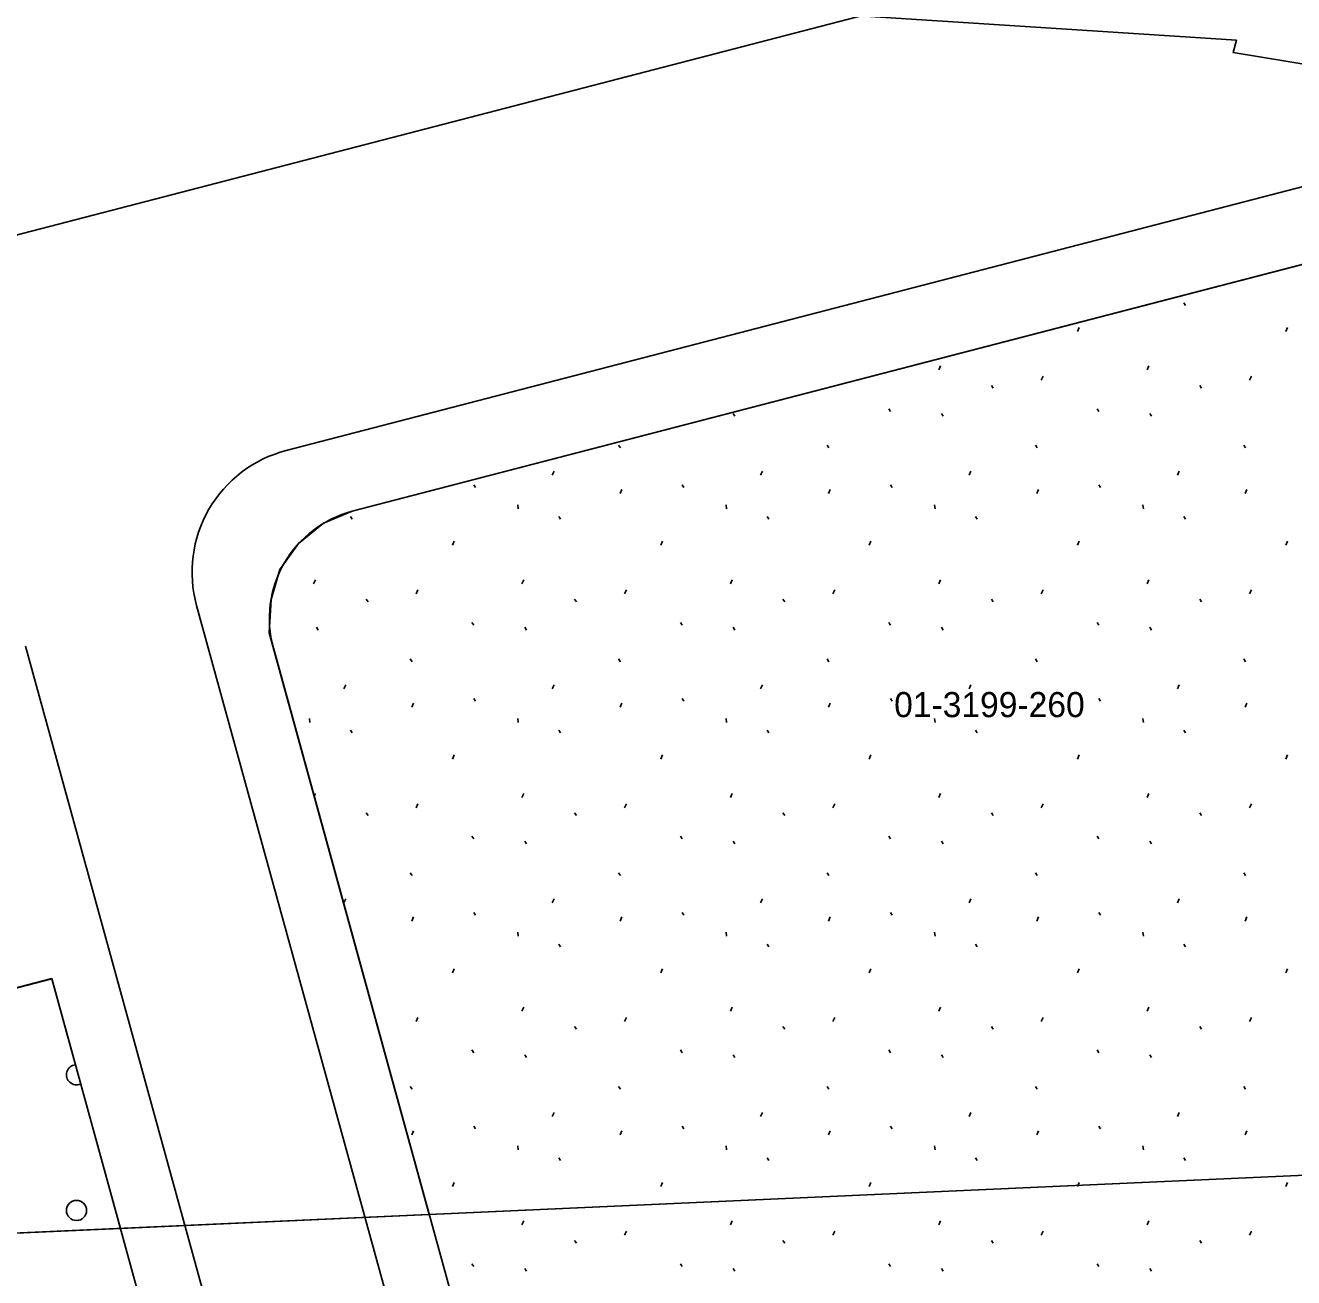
# Model space of a CAD drawing. Extents: x 419396 to 421519, y 4453567 to 4456767.
# Drawn here: x 421061.6 to 421112.1, y 4454776.6 to 4454826.5 of the extents above; entities that cross this region are included whole.
import ezdxf

# ---------------------------------------------------------------- set-up
doc = ezdxf.new("R2010")
doc.units = 0
for name, color, linetype in [('0_KADASTRO', 7, 'Continuous'), ('Level 28', 7, 'Continuous'), ('Level 41', 7, 'Continuous'), ('Level 43', 7, 'Continuous'), ('Level 62', 7, 'Continuous')]:
    doc.layers.add(name, color=color, linetype=linetype)

msp = doc.modelspace()

# ---------------------------------------------------------------- linework, layer by layer
at = {"layer": '0_KADASTRO'}
for points in [[(421028.757, 4454779.729), (421031.18, 4454814.37), (421031.268, 4454815.21), (421037.79, 4454815.4), (421037.91, 4454827.443), (421072.693, 4454827.787), (421077.33, 4454827.7), (421089.42, 4454827.23), (421092.96, 4454826.99), (421103.25, 4454826.33), (421109.8, 4454825.9), (421109.67, 4454825.41), (421112.98, 4454824.87), (421121.89, 4454821.45), (421122.04, 4454819.47), (421074.61, 4454807.15), (421073.47, 4454806.68), (421072.47, 4454805.87), (421071.73, 4454804.83), (421071.38, 4454803.63), (421071.31, 4454802.31), (421077.68, 4454779.15), (421065.39, 4454778.6), (421062.65, 4454788.54)], [(421071.31, 4454802.31), (421071.38, 4454803.63), (421071.73, 4454804.83), (421072.47, 4454805.87), (421073.47, 4454806.68), (421074.61, 4454807.15), (421122.04, 4454819.47), (421122.53, 4454812.93), (421122.63, 4454800.46), (421122.46, 4454786.27), (421122.61, 4454779.98), (421116.99, 4454780.91), (421077.68, 4454779.15)], [(421028.563, 4454776.952), (421028.757, 4454779.729), (421062.65, 4454788.54), (421065.39, 4454778.6)]]:
    msp.add_lwpolyline(points, close=True, dxfattribs=at)
msp.add_lwpolyline([(420970.25, 4454598.21), (420978.09, 4454629.67), (420985.81, 4454647.83), (420992.78, 4454658.3), (420990.74, 4454672.41), (420973.683, 4454711.074), (420973.63, 4454711.21), (420957.38, 4454751.82), (420949.17, 4454769.71), (421010.39, 4454774.36), (421028.563, 4454776.952), (421116.99, 4454780.91)], dxfattribs=at)
at = {"layer": 'Level 28'}
for p, q in [((421074.613, 4454807.147), (421123.795, 4454819.928)), ((421092.049, 4454726.945), (421071.472, 4454801.712)), ((420975.535, 4454765.902), (421062.651, 4454788.541)), ((421062.651, 4454788.541), (421085.345, 4454706.078))]:
    msp.add_line(p, q, dxfattribs=at)
msp.add_arc((421075.722, 4454802.881), 4.408, 104.5669, 195.3875, dxfattribs=at)
at = {"layer": 'Level 41'}
for p, q in [((421110.152, 4454816.366), (421110.161, 4454816.386)), ((421107.712, 4454815.45), (421107.782, 4454815.343)), ((421103.475, 4454814.306), (421103.547, 4454814.466)), ((421111.768, 4454814.306), (421111.84, 4454814.466)), ((421097.954, 4454812.776), (421098.024, 4454812.936)), ((421106.247, 4454812.776), (421106.317, 4454812.936)), ((421102.037, 4454812.368), (421102.108, 4454812.528)), ((421110.33, 4454812.368), (421110.401, 4454812.528)), ((421100.049, 4454812.16), (421100.12, 4454812.054)), ((421108.342, 4454812.16), (421108.413, 4454812.054)), ((421089.77, 4454811.039), (421089.841, 4454810.932)), ((421095.964, 4454811.231), (421096.035, 4454811.124)), ((421098.063, 4454811.039), (421098.134, 4454810.932)), ((421104.257, 4454811.231), (421104.328, 4454811.124)), ((421106.356, 4454811.039), (421106.427, 4454810.932)), ((421085.215, 4454809.778), (421085.286, 4454809.671)), ((421093.508, 4454809.778), (421093.579, 4454809.671)), ((421101.801, 4454809.778), (421101.872, 4454809.671)), ((421110.094, 4454809.778), (421110.165, 4454809.671)), ((421082.574, 4454808.585), (421082.645, 4454808.744)), ((421090.867, 4454808.585), (421090.938, 4454808.744)), ((421099.16, 4454808.585), (421099.231, 4454808.744)), ((421107.453, 4454808.585), (421107.524, 4454808.744)), ((421079.445, 4454808.201), (421079.516, 4454808.094)), ((421085.273, 4454807.856), (421085.345, 4454808.016)), ((421087.738, 4454808.201), (421087.809, 4454808.094)), ((421093.566, 4454807.856), (421093.638, 4454808.016)), ((421096.031, 4454808.201), (421096.102, 4454808.094)), ((421101.859, 4454807.856), (421101.931, 4454808.016)), ((421104.324, 4454808.201), (421104.395, 4454808.094)), ((421110.152, 4454807.856), (421110.224, 4454808.016)), ((421081.203, 4454807.41), (421081.221, 4454807.25)), ((421089.496, 4454807.41), (421089.514, 4454807.25)), ((421097.789, 4454807.41), (421097.807, 4454807.25)), ((421106.082, 4454807.41), (421106.1, 4454807.25)), ((421074.54, 4454806.94), (421074.61, 4454806.833)), ((421082.833, 4454806.94), (421082.903, 4454806.833)), ((421091.126, 4454806.94), (421091.196, 4454806.833)), ((421099.419, 4454806.94), (421099.489, 4454806.833)), ((421107.712, 4454806.94), (421107.782, 4454806.833)), ((421078.596, 4454805.796), (421078.668, 4454805.956)), ((421086.889, 4454805.796), (421086.961, 4454805.956)), ((421095.182, 4454805.796), (421095.254, 4454805.956)), ((421103.475, 4454805.796), (421103.547, 4454805.956)), ((421111.768, 4454805.796), (421111.84, 4454805.956)), ((421073.075, 4454804.266), (421073.145, 4454804.426)), ((421081.368, 4454804.266), (421081.438, 4454804.426)), ((421089.661, 4454804.266), (421089.731, 4454804.426)), ((421097.954, 4454804.266), (421098.024, 4454804.426)), ((421106.247, 4454804.266), (421106.317, 4454804.426)), ((421077.158, 4454803.858), (421077.229, 4454804.018)), ((421085.451, 4454803.858), (421085.522, 4454804.018)), ((421093.744, 4454803.858), (421093.815, 4454804.018)), ((421102.037, 4454803.858), (421102.108, 4454804.018)), ((421110.33, 4454803.858), (421110.401, 4454804.018)), ((421075.17, 4454803.65), (421075.241, 4454803.544)), ((421083.463, 4454803.65), (421083.534, 4454803.544)), ((421091.756, 4454803.65), (421091.827, 4454803.544)), ((421100.049, 4454803.65), (421100.12, 4454803.544)), ((421108.342, 4454803.65), (421108.413, 4454803.544)), ((421073.184, 4454802.529), (421073.255, 4454802.422)), ((421079.378, 4454802.721), (421079.449, 4454802.614)), ((421081.477, 4454802.529), (421081.548, 4454802.422)), ((421087.671, 4454802.721), (421087.742, 4454802.614)), ((421089.77, 4454802.529), (421089.841, 4454802.422)), ((421095.964, 4454802.721), (421096.035, 4454802.614)), ((421098.063, 4454802.529), (421098.134, 4454802.422)), ((421104.257, 4454802.721), (421104.328, 4454802.614)), ((421106.356, 4454802.529), (421106.427, 4454802.422)), ((421076.922, 4454801.268), (421076.993, 4454801.161)), ((421085.215, 4454801.268), (421085.286, 4454801.161)), ((421093.508, 4454801.268), (421093.579, 4454801.161)), ((421101.801, 4454801.268), (421101.872, 4454801.161)), ((421110.094, 4454801.268), (421110.165, 4454801.161)), ((421074.281, 4454800.075), (421074.352, 4454800.234)), ((421082.574, 4454800.075), (421082.645, 4454800.234)), ((421090.867, 4454800.075), (421090.938, 4454800.234)), ((421099.16, 4454800.075), (421099.231, 4454800.234)), ((421107.453, 4454800.075), (421107.524, 4454800.234)), ((421076.98, 4454799.346), (421077.052, 4454799.506)), ((421079.445, 4454799.691), (421079.516, 4454799.584)), ((421085.273, 4454799.346), (421085.345, 4454799.506)), ((421087.738, 4454799.691), (421087.809, 4454799.584)), ((421093.566, 4454799.346), (421093.638, 4454799.506)), ((421096.031, 4454799.691), (421096.102, 4454799.584)), ((421101.859, 4454799.346), (421101.931, 4454799.506)), ((421104.324, 4454799.691), (421104.395, 4454799.584)), ((421110.152, 4454799.346), (421110.224, 4454799.506)), ((421072.91, 4454798.9), (421072.928, 4454798.74)), ((421081.203, 4454798.9), (421081.221, 4454798.74)), ((421089.496, 4454798.9), (421089.514, 4454798.74)), ((421097.789, 4454798.9), (421097.807, 4454798.74)), ((421106.082, 4454798.9), (421106.1, 4454798.74)), ((421074.54, 4454798.43), (421074.61, 4454798.323)), ((421082.833, 4454798.43), (421082.903, 4454798.323)), ((421091.126, 4454798.43), (421091.196, 4454798.323)), ((421099.419, 4454798.43), (421099.489, 4454798.323)), ((421107.712, 4454798.43), (421107.782, 4454798.323)), ((421078.596, 4454797.286), (421078.668, 4454797.446)), ((421086.889, 4454797.286), (421086.961, 4454797.446)), ((421095.182, 4454797.286), (421095.254, 4454797.446)), ((421103.475, 4454797.286), (421103.547, 4454797.446)), ((421111.768, 4454797.286), (421111.84, 4454797.446)), ((421073.098, 4454795.808), (421073.145, 4454795.916)), ((421081.368, 4454795.756), (421081.438, 4454795.916)), ((421089.661, 4454795.756), (421089.731, 4454795.916)), ((421097.954, 4454795.756), (421098.024, 4454795.916)), ((421106.247, 4454795.756), (421106.317, 4454795.916)), ((421077.158, 4454795.348), (421077.229, 4454795.508)), ((421085.451, 4454795.348), (421085.522, 4454795.508)), ((421093.744, 4454795.348), (421093.815, 4454795.508)), ((421102.037, 4454795.348), (421102.108, 4454795.508)), ((421110.33, 4454795.348), (421110.401, 4454795.508)), ((421075.17, 4454795.14), (421075.241, 4454795.034)), ((421083.463, 4454795.14), (421083.534, 4454795.034)), ((421091.756, 4454795.14), (421091.827, 4454795.034)), ((421100.049, 4454795.14), (421100.12, 4454795.034)), ((421108.342, 4454795.14), (421108.413, 4454795.034)), ((421079.378, 4454794.211), (421079.449, 4454794.104)), ((421087.671, 4454794.211), (421087.742, 4454794.104)), ((421095.964, 4454794.211), (421096.035, 4454794.104)), ((421104.257, 4454794.211), (421104.328, 4454794.104)), ((421081.477, 4454794.019), (421081.548, 4454793.912)), ((421089.77, 4454794.019), (421089.841, 4454793.912)), ((421098.063, 4454794.019), (421098.134, 4454793.912)), ((421106.356, 4454794.019), (421106.427, 4454793.912)), ((421076.922, 4454792.758), (421076.993, 4454792.651)), ((421085.215, 4454792.758), (421085.286, 4454792.651)), ((421093.508, 4454792.758), (421093.579, 4454792.651)), ((421101.801, 4454792.758), (421101.872, 4454792.651)), ((421110.094, 4454792.758), (421110.165, 4454792.651)), ((421074.281, 4454791.565), (421074.352, 4454791.724)), ((421082.574, 4454791.565), (421082.645, 4454791.724)), ((421090.867, 4454791.565), (421090.938, 4454791.724)), ((421099.16, 4454791.565), (421099.231, 4454791.724)), ((421107.453, 4454791.565), (421107.524, 4454791.724)), ((421079.445, 4454791.181), (421079.516, 4454791.074)), ((421087.738, 4454791.181), (421087.809, 4454791.074)), ((421096.031, 4454791.181), (421096.102, 4454791.074)), ((421104.324, 4454791.181), (421104.395, 4454791.074)), ((421076.98, 4454790.836), (421077.052, 4454790.996)), ((421085.273, 4454790.836), (421085.345, 4454790.996)), ((421093.566, 4454790.836), (421093.638, 4454790.996)), ((421101.859, 4454790.836), (421101.931, 4454790.996)), ((421110.152, 4454790.836), (421110.224, 4454790.996)), ((421081.203, 4454790.39), (421081.221, 4454790.23)), ((421089.496, 4454790.39), (421089.514, 4454790.23)), ((421097.789, 4454790.39), (421097.807, 4454790.23)), ((421106.082, 4454790.39), (421106.1, 4454790.23)), ((421082.833, 4454789.92), (421082.903, 4454789.813)), ((421091.126, 4454789.92), (421091.196, 4454789.813)), ((421099.419, 4454789.92), (421099.489, 4454789.813)), ((421107.712, 4454789.92), (421107.782, 4454789.813)), ((421078.596, 4454788.776), (421078.668, 4454788.936)), ((421086.889, 4454788.776), (421086.961, 4454788.936)), ((421095.182, 4454788.776), (421095.254, 4454788.936)), ((421103.475, 4454788.776), (421103.547, 4454788.936)), ((421111.768, 4454788.776), (421111.84, 4454788.936)), ((421081.368, 4454787.246), (421081.438, 4454787.406)), ((421089.661, 4454787.246), (421089.731, 4454787.406)), ((421097.954, 4454787.246), (421098.024, 4454787.406)), ((421106.247, 4454787.246), (421106.317, 4454787.406)), ((421077.158, 4454786.838), (421077.229, 4454786.998)), ((421083.463, 4454786.63), (421083.534, 4454786.524)), ((421085.451, 4454786.838), (421085.522, 4454786.998)), ((421091.756, 4454786.63), (421091.827, 4454786.524)), ((421093.744, 4454786.838), (421093.815, 4454786.998)), ((421100.049, 4454786.63), (421100.12, 4454786.524)), ((421102.037, 4454786.838), (421102.108, 4454786.998)), ((421108.342, 4454786.63), (421108.413, 4454786.524)), ((421110.33, 4454786.838), (421110.401, 4454786.998)), ((421079.378, 4454785.701), (421079.449, 4454785.594)), ((421087.671, 4454785.701), (421087.742, 4454785.594)), ((421095.964, 4454785.701), (421096.035, 4454785.594)), ((421104.257, 4454785.701), (421104.328, 4454785.594)), ((421081.477, 4454785.509), (421081.548, 4454785.402)), ((421089.77, 4454785.509), (421089.841, 4454785.402)), ((421098.063, 4454785.509), (421098.134, 4454785.402)), ((421106.356, 4454785.509), (421106.427, 4454785.402)), ((421076.922, 4454784.248), (421076.993, 4454784.141)), ((421085.215, 4454784.248), (421085.286, 4454784.141)), ((421093.508, 4454784.248), (421093.579, 4454784.141)), ((421101.801, 4454784.248), (421101.872, 4454784.141)), ((421110.094, 4454784.248), (421110.165, 4454784.141)), ((421082.574, 4454783.055), (421082.645, 4454783.214)), ((421090.867, 4454783.055), (421090.938, 4454783.214)), ((421099.16, 4454783.055), (421099.231, 4454783.214)), ((421107.453, 4454783.055), (421107.524, 4454783.214)), ((421079.445, 4454782.671), (421079.516, 4454782.564)), ((421087.738, 4454782.671), (421087.809, 4454782.564)), ((421096.031, 4454782.671), (421096.102, 4454782.564)), ((421104.324, 4454782.671), (421104.395, 4454782.564)), ((421076.98, 4454782.326), (421077.052, 4454782.486)), ((421085.273, 4454782.326), (421085.345, 4454782.486)), ((421093.566, 4454782.326), (421093.638, 4454782.486)), ((421101.859, 4454782.326), (421101.931, 4454782.486)), ((421110.152, 4454782.326), (421110.224, 4454782.486)), ((421081.203, 4454781.88), (421081.221, 4454781.72)), ((421089.496, 4454781.88), (421089.514, 4454781.72)), ((421097.789, 4454781.88), (421097.807, 4454781.72)), ((421106.082, 4454781.88), (421106.1, 4454781.72)), ((421082.833, 4454781.41), (421082.903, 4454781.303)), ((421091.126, 4454781.41), (421091.196, 4454781.303)), ((421099.419, 4454781.41), (421099.489, 4454781.303)), ((421107.712, 4454781.41), (421107.782, 4454781.303)), ((421078.596, 4454780.266), (421078.668, 4454780.426)), ((421086.889, 4454780.266), (421086.961, 4454780.426)), ((421095.182, 4454780.266), (421095.254, 4454780.426)), ((421103.475, 4454780.266), (421103.547, 4454780.426)), ((421111.768, 4454780.266), (421111.84, 4454780.426)), ((421081.368, 4454778.736), (421081.438, 4454778.896)), ((421089.661, 4454778.736), (421089.731, 4454778.896)), ((421097.954, 4454778.736), (421098.024, 4454778.896)), ((421106.247, 4454778.736), (421106.317, 4454778.896)), ((421083.463, 4454778.12), (421083.534, 4454778.014)), ((421085.451, 4454778.328), (421085.522, 4454778.488)), ((421091.756, 4454778.12), (421091.827, 4454778.014)), ((421093.744, 4454778.328), (421093.815, 4454778.488)), ((421100.049, 4454778.12), (421100.12, 4454778.014)), ((421102.037, 4454778.328), (421102.108, 4454778.488)), ((421108.342, 4454778.12), (421108.413, 4454778.014)), ((421110.33, 4454778.328), (421110.401, 4454778.488)), ((421079.378, 4454777.191), (421079.449, 4454777.084)), ((421081.477, 4454776.999), (421081.548, 4454776.892)), ((421087.671, 4454777.191), (421087.742, 4454777.084)), ((421089.77, 4454776.999), (421089.841, 4454776.892)), ((421095.964, 4454777.191), (421096.035, 4454777.084)), ((421098.063, 4454776.999), (421098.134, 4454776.892)), ((421104.257, 4454777.191), (421104.328, 4454777.084)), ((421106.356, 4454776.999), (421106.427, 4454776.892))]:
    msp.add_line(p, q, dxfattribs=at)
at = {"layer": 'Level 43'}
msp.add_circle((421063.637, 4454779.314), 0.4, dxfattribs=at)
msp.add_arc((421063.637, 4454784.714), 0.4, 96.1094, 294.6663, dxfattribs=at)
at = {"layer": 'Level 62'}
for p, q in [((421133.75, 4454836.983), (420969.706, 4454794.354)), ((421124.964, 4454823.334), (421071.979, 4454809.565)), ((421090.256, 4454724.041), (421068.415, 4454803.399)), ((421084.335, 4454719.175), (421061.602, 4454801.777))]:
    msp.add_line(p, q, dxfattribs=at)
msp.add_arc((421073.236, 4454804.726), 5, 104.5669, 195.3875, dxfattribs=at)

# ---------------------------------------------------------------- texts
at = {"layer": '0_KADASTRO'}
msp.add_text('01-3199-260', height=1, dxfattribs=at).set_placement((421096.181, 4454798.952))

doc.saveas('drawing.dxf')
